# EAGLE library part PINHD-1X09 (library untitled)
PIN HEADER
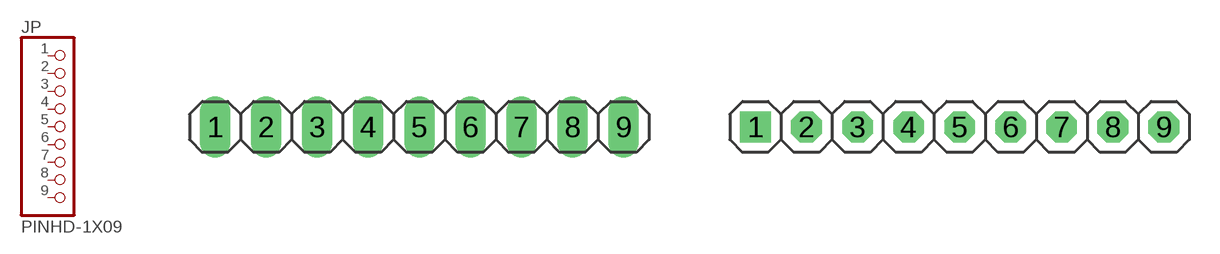
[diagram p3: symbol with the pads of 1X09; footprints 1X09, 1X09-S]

Designator prefix JP

## PINHD-1X09_2.54  [1X09]
1  1  pas
2  2  pas
3  3  pas
4  4  pas
5  5  pas
6  6  pas
7  7  pas
8  8  pas
9  9  pas

## PINHD-1X09_2.54-S  [1X09-S]
Pads as for 1X09

## PINHD-1X09_2.54-90°  [1X09/90]
Pads as for 1X09

## PINHD-1X09_2.54-90°-S  [1X09/90-S]
Pads as for 1X09

## PINHD-1X09_2.00  [1X09M]
Pads as for 1X09

## PINHD-1X09_2.54-SMD  [1X09SMD]
Pads as for 1X09

## PINHD-1X09_2.54-SMD-90°  [1X09SMD/90]
Pads as for 1X09

## Footprint 1X09 (pad centres in mm)
PIN HEADER - 2.54
drill 1.016 long: 1 -10.16,0; 2 -7.62,0; 3 -5.08,0; 4 -2.54,0; 5 0,0; 6 2.54,0; 7 5.08,0; 8 7.62,0; 9 10.16,0

## Footprint 1X09-S (pad centres in mm)
PIN HEADER - 2.54
drill 1.016 square: 1 -10.16,0
drill 1.016 octagon: 2 -7.62,0; 3 -5.08,0; 4 -2.54,0; 5 0,0; 6 2.54,0; 7 5.08,0; 8 7.62,0; 9 10.16,0

## Footprint 1X09/90 (pad centres in mm)
PIN HEADER - 2.54 90°
drill 1.016 long: 1 -10.16,-3.81; 2 -7.62,-3.81; 3 -5.08,-3.81; 4 -2.54,-3.81; 5 0,-3.81; 6 2.54,-3.81; 7 5.08,-3.81; 8 7.62,-3.81; 9 10.16,-3.81

## Footprint 1X09/90-S (pad centres in mm)
PIN HEADER - 2.54 90°
drill 1.016 square: 1 -10.16,-3.81
drill 1.016 octagon: 2 -7.62,-3.81; 3 -5.08,-3.81; 4 -2.54,-3.81; 5 0,-3.81; 6 2.54,-3.81; 7 5.08,-3.81; 8 7.62,-3.81; 9 10.16,-3.81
